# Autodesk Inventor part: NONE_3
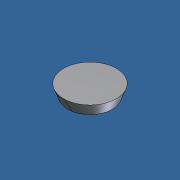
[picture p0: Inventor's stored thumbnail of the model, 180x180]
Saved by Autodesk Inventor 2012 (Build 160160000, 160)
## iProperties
Created: 2013-10
Part Number: NONE_3
Material: Default
Document SubType Name: Modeling
Designer: Admin
Density: 1 g/cm^3
Author: Admin
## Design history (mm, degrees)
node "Sankq_7011P566_Handle1"
node "Base1"
body "Solid1"
